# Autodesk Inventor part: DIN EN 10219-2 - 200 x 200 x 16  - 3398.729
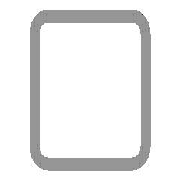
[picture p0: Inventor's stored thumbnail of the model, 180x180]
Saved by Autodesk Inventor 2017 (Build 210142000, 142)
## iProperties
IsCustomPart: 1
_CCFamilyMember: 103
_CCFamilyDisplayName: DIN EN 10219-2 (Square Hollow Section - Cold Formed) - Cold formed welded structural hollow sections of non-alloy and fine grain structural steel
_FrameMemberDoc: Frame Member File
_Version: 15.0.0
_GetPNFromCC: 1
Created: 2016-02
Part Number: DIN EN 10219-2 - 200 x 200 x 16  - 3398.729
Material: Steel, Mild
Description: Cold formed welded structural hollow sections of non-alloy and fine grain structural steel
Document SubType Name: Modeling
Standard: DIN
Designer: iusti
Standard Revision: 2006-07
Standards Organization: DIN
Language: en-US
Size Designation: 200 x 200 x 16
Categories: <MemberInstance><Categories><Category DisplayName="Structural Shapes" InternalName="089c4875-fa83-4c05-b084-43b9cc11f5ed" Mnemonic="GRDR"><CategoryParameter Dis
Stock Number: 200 x 200 x 16
Density: 7.85 g/cm^3
Appearance: Semi-Polished
Mass: 260009 g
Surface Area: 41812.5 cm^2
Volume: 33122.1 cm^3
G_L: 3398.729 mm
G_W: 200.000 mm
G_H: 200.000 mm
+A2FA36FB-A031-4659-8CB0-A5A84C4F6311+CUTDETAIL1: Cut
+96BC65A8-7812-439C-A6F9-D3AF540F1DD0+CUTDETAIL2: Cut
Author: iusti
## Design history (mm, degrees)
node "Start plane"
node "End plane"
sketch "Sketch"
  geometry: L1 (-100, -52)-(-100, 52); L2 (-52, 100)-(52, 100); L3 (100, 52)-(100, -52); L4 (52, -100)-(-52, -100); L5 (-52, 84)-(52, 84); L6 (84, 52)-(84, -52); L7 (52, -84)-(-52, -84); L8 (-84, -52)-(-84, 52); L9 (0, 153.918)-(0, -153.918) reference; L10 (-153.918, 0)-(153.918, 0) reference; A1 r 48 centre (-52, -52) between (-100, -52) and (-52, -100); A2 r 48 centre (-52, 52) between (-52, 100) and (-100, 52); A3 r 48 centre (52, 52) between (100, 52) and (52, 100); A4 r 48 centre (52, -52) between (52, -100) and (100, -52); A5 r 32 centre (-52, 52) between (-52, 84) and (-84, 52); A6 r 32 centre (52, 52) between (84, 52) and (52, 84); A7 r 32 centre (52, -52) between (52, -84) and (84, -52); A8 r 32 centre (-52, -52) between (-84, -52) and (-52, -84)
  constraints: 16 end point, 16 point on circle, 8 centre point, 8 tangent, 4 parallel, 3 equal radius, 2 perpendicular, 7 other
  dimensions: "d7" = 48 radius of A1 (= G_IR); "d10" = 200 distance between parallel lines of L2 L4 (= G_H); "d11" = 200 distance between parallel lines of L1 L3 (= G_W); "d12" = 16 distance between parallel lines of L3 L6 (= G_T); "d15" = 100 distance between parallel lines of L2 L10 (= 0.5 x d10); "d16" = 100 distance between parallel lines of L9 L3 (= 0.5 x d11)
extrude "Body" new body sketch "Sketch" stored distance "d3" = 3398.72851 (= G_L); taper "d4" = 0 deg
node "Driven Length"
  sketch "Sketch3"
    geometry: L1 (0, 0)-(10, 0) reference
    constraints: 2 end point, 1 horizontal
  workplane "Work Plane3"
  sketch "Sketch4"
    geometry: L1 (-2, 18.715)-(12, 18.715) reference; L2 (-2, 3417.443)-(12, 3417.443) reference
    dimensions: "d18" = 3398.72851 distance between parallel lines of L1 L2 (derived)
workplane "Work Plane4"
split "Split1"
workplane "Work Plane5"
split "Split2"
body "Solid1"
other parameters: "G_W" = 200 [user parameter; used in 1 equation term], "G_H" = 200 [user parameter; used in 1 equation term], "G_T" = 16 [user parameter; used in 1 equation term], "G_IR" = 48 [user parameter; used in 1 equation term], "G_L" = 3398.72851 (= d18) [user parameter; used in 1 equation term], "G_OFFSET_START" = -18.71453 [user parameter; used in 1 equation term], "G_OFFSET_END" = -39.1736 [user parameter; used in 1 equation term], "d13" = 18.71453 (= -G_OFFSET_START), "d14" = 3417.44304 (= G_OFFSET_END + B_L), "B_L" = 3456.61664 [user parameter; used in 1 equation term], "d17" = 90 deg
